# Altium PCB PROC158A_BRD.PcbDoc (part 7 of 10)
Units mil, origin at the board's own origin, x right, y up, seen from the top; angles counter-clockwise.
Board outline 3346.45 x 4921.26 mil, 8 copper layers (Top Layer, GND1, SIG1, PWR1, PWR2, SIG2, GND2, Bottom Layer), stack 54.534 mil thick; 718 components, 459 nets, 2307 pads, 1179 vias.
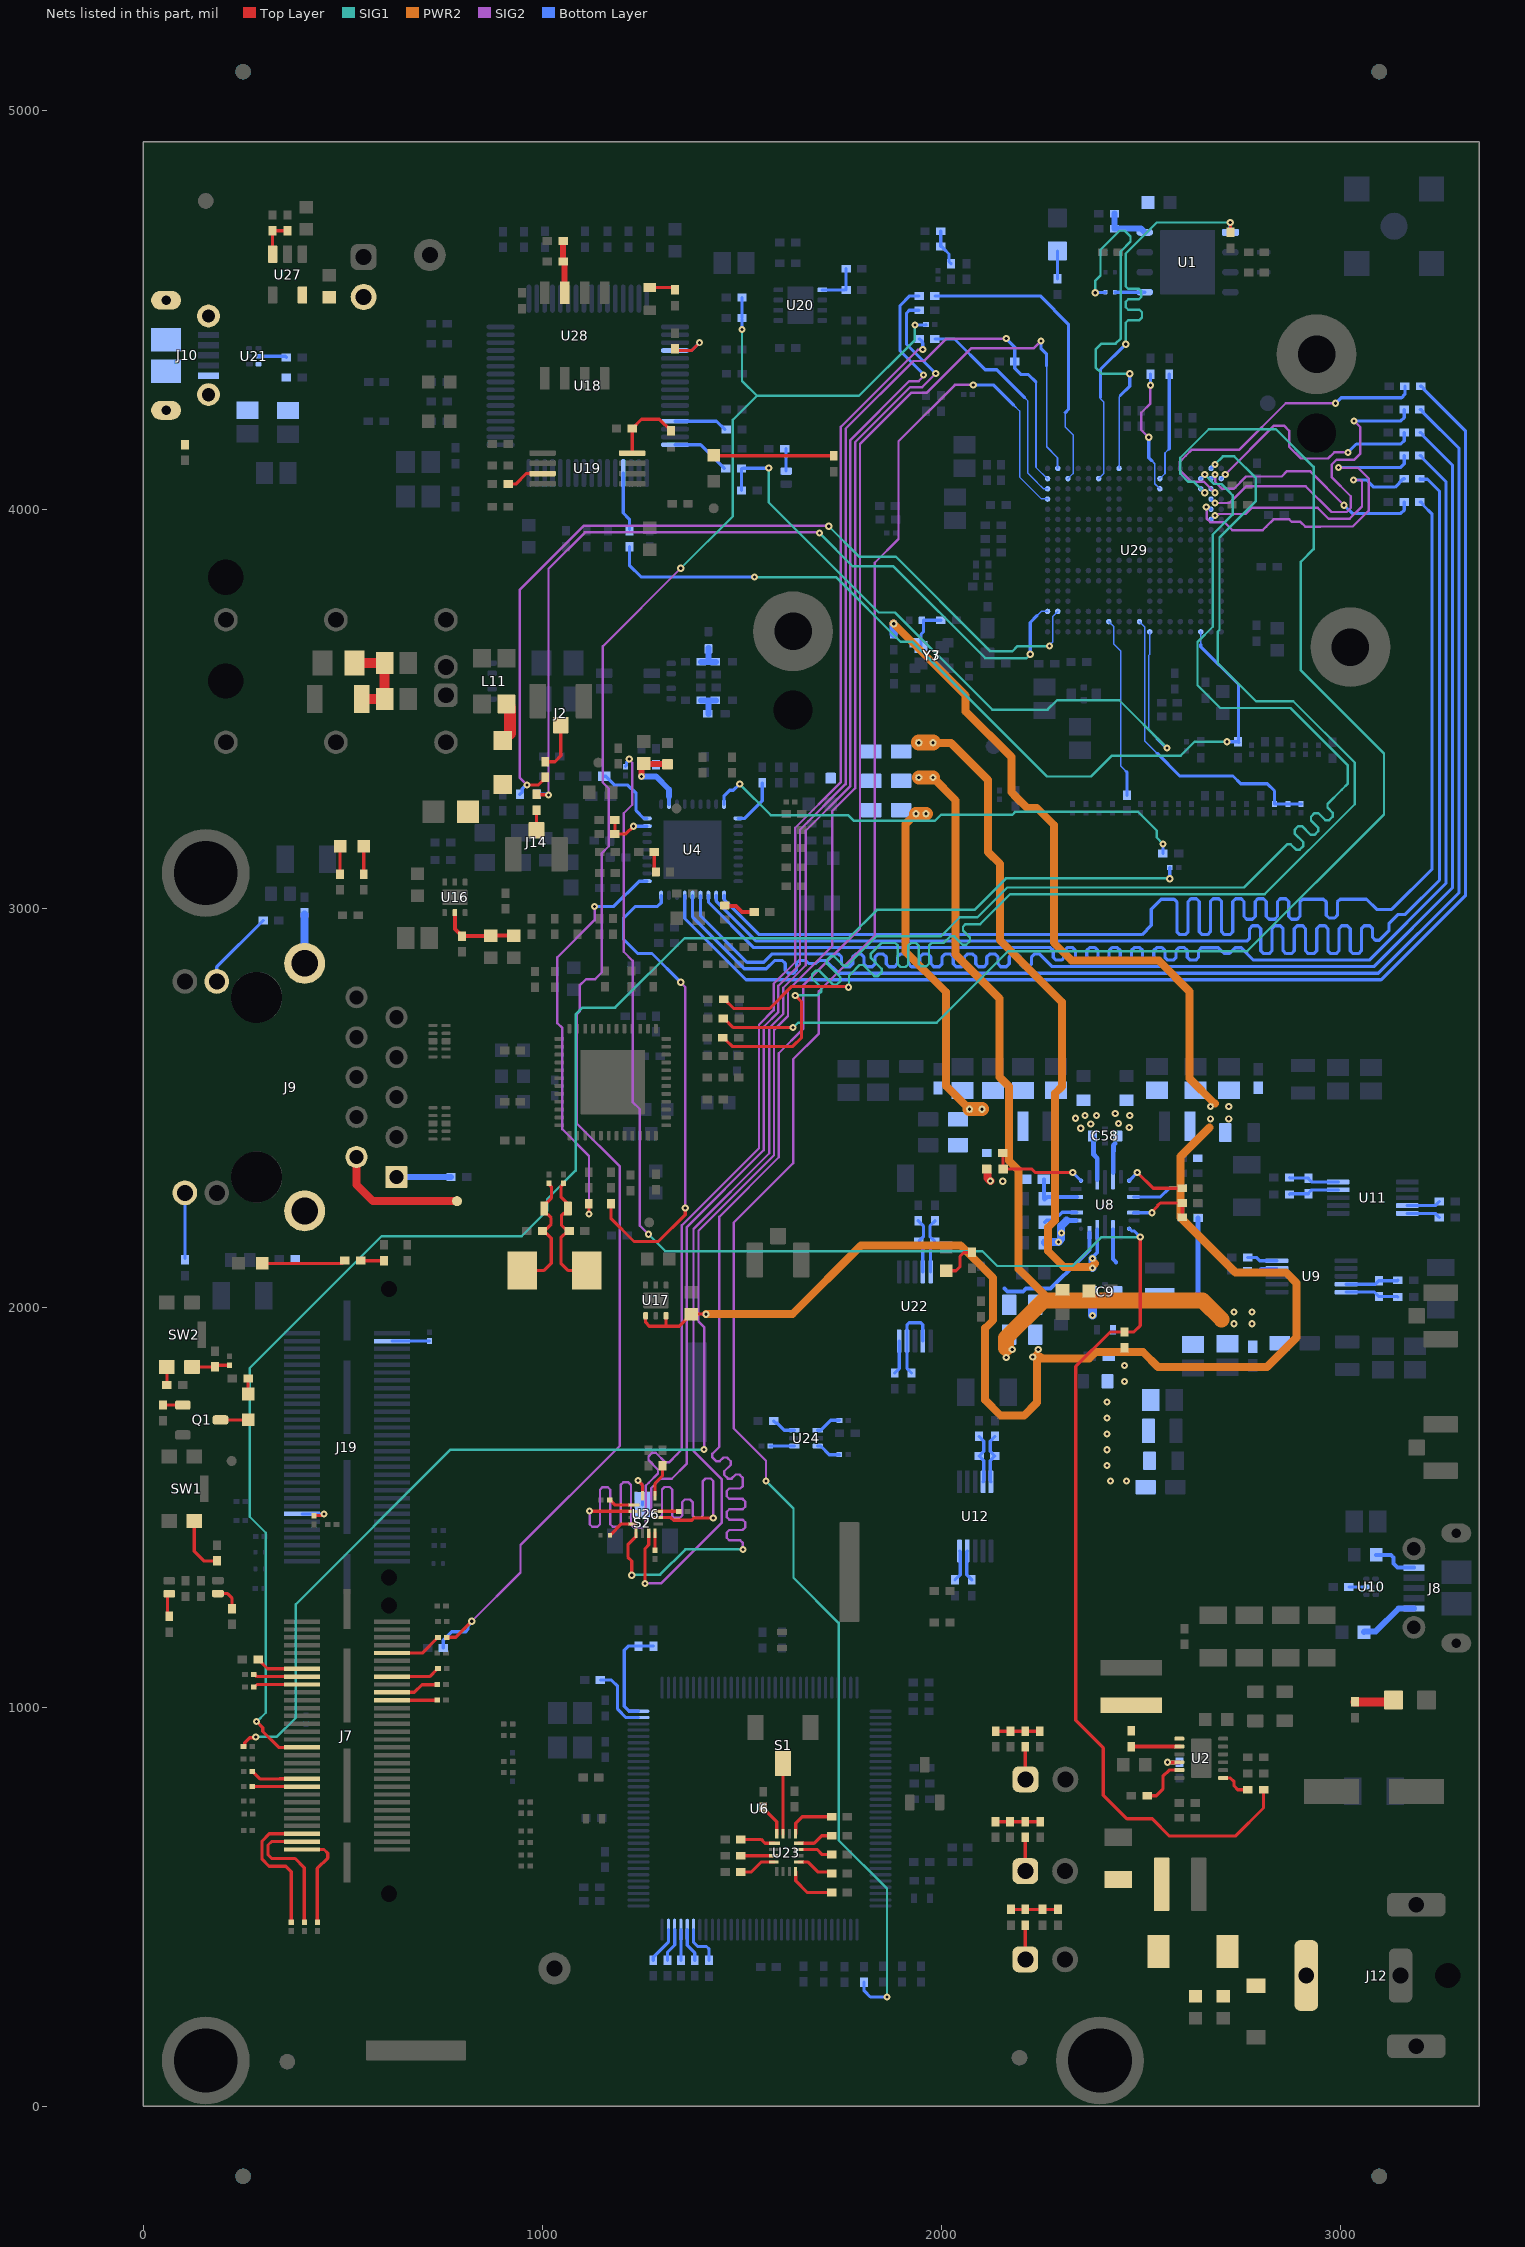
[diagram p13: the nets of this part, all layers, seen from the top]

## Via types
v1: diameter 18, hole 8, Top Layer to Bottom Layer, tented both sides, 1112 vias
v2: diameter 19.68, hole 7.87, Top Layer to Bottom Layer, 28 vias
v3: diameter 20, hole 10, Top Layer to Bottom Layer, tented both sides, 26 vias
v4: diameter 16/18/18/18/18/18/18/16 (per signal layer), hole 8, Top Layer to Bottom Layer, tented both sides, 13 vias

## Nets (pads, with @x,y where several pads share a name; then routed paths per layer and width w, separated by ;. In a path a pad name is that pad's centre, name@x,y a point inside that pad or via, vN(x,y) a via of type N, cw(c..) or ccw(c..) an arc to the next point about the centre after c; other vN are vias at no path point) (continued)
MSS_RGMII_RD1: R238.1 R336.1 U29.T16 | length 3422.1
  Top Layer w8: R336.1@1451.99,2676.6 1453.96,2676.6 1459.8,2670.76 1459.8,2670.39 1475.19,2655 1627.29,2655 1649,2676.71 1649,2767.02 v1(1633.15,2782.87)
  SIG1 w6: v1(1633.15,2782.87) 1688.91,2782.87 1696.81,2790.76 1698.93,2792.89 1698.93,2802.08 1675.22,2825.79 1675.22,2834.98 1684.41,2844.17 1693.6,2844.17 1728.07,2809.7 1737.26,2809.7 1746.45,2818.9 1746.45,2828.09 1712.53,2862.02 1712.53,2871.21 1721.72,2880.4 1730.91,2880.4 1754.08,2857.23 1763.27,2857.23 1792.19,2886.15 1837.04,2931 1998,2931 2045.45,2978.45 2089.55,2978.45 2164.23,3053.13 2757.4,3053.13 2844.95,3140.68 2865.46,3161.19 2874.65,3161.19 2887.82,3148.02 2897.02,3148.02 2906.21,3157.21 2906.21,3166.4 2884.27,3188.34 2884.27,3197.53 2893.46,3206.72 2902.66,3206.72 2924.59,3184.79 2933.79,3184.79 2942.98,3193.98 2942.98,3203.17 2925.16,3220.99 2925.16,3230.18 2934.35,3239.38 2943.54,3239.38 2961.36,3221.56 2970.56,3221.56 2979.75,3230.75 2979.75,3239.94 2966.58,3253.11 2966.58,3262.3 3002.1,3297.83 3017.79,3313.52 3017.79,3358.8 2873.94,3502.64 2698.12,3502.64 2640.9,3559.86 2640.9,3668.14 2679,3706.24 2679,3937.04 2729,3987.04 2729,4035.79 2718.86,4045.93 2700.79,4064 2682.39,4064 v4(2659.08,4087.31)
  Bottom Layer w6: U29.T16@2649.16,4077.38 v4(2659.08,4087.31)
MSS_RGMII_RD2: R239.1 R338.1 U29.R16 | length 3393.7
  Top Layer w8: R338.1@1453.43,2724.89 1455.4,2724.89 1478.29,2702 v1(1628,2702)
  SIG1 w6: v1(1628,2702) 1628.14,2702.04 1640.78,2714.68 1987.68,2714.68 2166.35,2893.35 2765.31,2893.35 3108.2,3236.24 3108.2,3388.59 2900,3596.79 2900,3869 2931.7,3900.7 2931.7,4106.7 2837.45,4200.95 2668.95,4200.95 2597.53,4129.53 2597.53,4089.49 2617.74,4069.29 2632.1,4069.29 2659.08,4042.3 v4(2659.08,4041.87)
  Bottom Layer w8: U29.R16@2649.16,4051.79 v4(2659.08,4041.87)
MSS_RGMII_RD3: R240.1 R339.1 U29.U17 | length 3379.8
  Top Layer w8: R339.1@1453.7,2773.09 1455.66,2773.09 1478.75,2750 1569.01,2750 1624.45,2805.44 1764.52,2805.44 v1(1766.91,2803.05)
  SIG1 w6: v1@1768.05,2804.11 1768.05,2832.58 1773.89,2838.41 1794.39,2858.92 1803.58,2858.92 1831.37,2831.13 1840.57,2831.13 1849.76,2840.32 1849.76,2849.52 1821.97,2877.31 1821.97,2886.5 1842.99,2907.52 1849.47,2914 1854.84,2914 1883.84,2914 1890.34,2907.5 1890.34,2860.48 1896.84,2853.98 1909.84,2853.98 1916.34,2860.48 1916.34,2907.5 1922.84,2914 1935.84,2914 1942.34,2907.5 1942.34,2862.15 1948.84,2855.65 1961.84,2855.65 1968.34,2862.15 1968.34,2907.5 1974.84,2914 1980.05,2914 1985.16,2914 2005.04,2914 2022.11,2931.07 2031.3,2931.07 2052.57,2909.8 2061.76,2909.8 2070.95,2918.99 2070.95,2928.18 2053.37,2945.76 2053.37,2954.95 2059.87,2961.45 2073.75,2961.45 2096.59,2961.45 2171.27,3036.13 2809.17,3036.13 3034.79,3261.74 3034.79,3365.84 2880.98,3519.64 2787.36,3519.64 2691.76,3615.24 2691.76,3694.11 2696,3698.34 2696,3930 2787.06,4021.06 2787.06,4079.08 2733.19,4132.95 2704.46,4132.95 2684.67,4113.16 v4(2684.67,4112.9)
  Bottom Layer w8: U29.U17@2674.75,4102.97 v4(2684.67,4112.9)
MSS_RGMII_TCLK: R74.1 R98.1 U29.T17 | length 599
  SIG2 w6: v4(2684.67,4087.31) 2685.22,4086.76 2685.22,4069.31 2702.41,4052.12 2718.86,4052.12 2732.23,4052.12 2762.8,4082.68 2851.8,4082.68 2865.32,4096.21 2922.39,4096.21 v1(3007.9,4010.7)
  Bottom Layer w8: U29.T17@2674.75,4077.38 v4(2684.67,4087.31) ; v1(3007.9,4010.7) 3028.44,3990.16 3150.38,3990.16 3158.63,3998.41 R98.1@3158.63,4019
MSS_RGMII_TCTL: R101.1 R230.1 U29.M17 | length 642.4
  SIG2 w6: v4(2684.67,3984.94) 2686.97,3987.24 2692.59,3987.24 2694.19,3988.84 2727.51,3988.84 2761.18,3988.84 2776.39,4004.05 2870,4004.05 2942.17,4004.05 2969.52,3976.7 3021.98,3976.7 3053,4007.72 3053,4070.49 3049.49,4074 v1(3032,4074)
  Bottom Layer w8: U29.M17@2674.88,3975.15 2684.19,3984.46 v4@2685.15,3984.46 ; v1(3032,4074) 3064.51,4074 3082.39,4056.13 3135.82,4056.13 3156.66,4076.97 R101.1@3158.63,4076.97
MSS_RGMII_TD0: R96.1 R103.1 U29.R17 | length 801.8
  SIG2 w6: v4(2684.67,4041.87) 2656.76,4069.78 2624.93,4069.78 2596,4098.72 2596,4119 2611.47,4134.47 2627,4150 2746,4150 2862,4266 v1(2987,4266)
  Bottom Layer w8: U29.R17@2674.75,4051.79 v4(2684.67,4041.87) ; v1(2987,4266) 3001,4280 3152.35,4280 3160.6,4288.25 R103.1@3160.6,4308.84
MSS_RGMII_TD1: R100.1 R105.1 U29.P17 | length 852.4
  SIG2 w6: v4(2684.67,4016.28) 2720.89,4016.28 2727.51,4022.89 2762.61,4058 2870,4058 2912.26,4058 2976.56,3993.7 3014.94,3993.7 3024.9,4003.66 3024.9,4033.1 2977,4081 2977,4112.04 2989.97,4125.01 3034.02,4125.01 3049.03,4140.02 3049.03,4205.97 v1(3033,4222)
  Bottom Layer w6: U29.P17@2674.75,4026.2 v4(2684.67,4016.28)
  Bottom Layer w8: v1(3033,4222) 3150.35,4222 3158.63,4230.28 R105.1@3158.63,4250.87
MSS_RGMII_TD2: R121.1 R178.1 U29.T18 | length 609.9
  SIG2 w6: v4(2710.26,4087.31) 2832.96,4210 2857.61,4210 2870.5,4197.11 2870.5,4157.09 2899.94,4127.66 2967.97,4127.66 2983.31,4143 v1(3018,4143)
  Bottom Layer w6: U29.T18@2700.34,4077.38 v4(2710.26,4087.31)
  Bottom Layer w8: v1(3018,4143) 3039,4164 3150.32,4164 3158.63,4172.31 R121.1@3158.63,4192.91
MSS_RGMII_TD3: R122.1 R225.1 U29.N17 | length 852.9
  SIG2 w6: v4@2663.83,4006.03 2663.83,3977.17 2673.06,3967.94 2708.38,3967.94 2728,3948.32 2804.28,3948.32 2812.98,3957.02 2831.28,3975.28 2870.78,3975.28 2877.18,3968.88 2898.96,3968.88 2910.69,3957.15 2948.85,3957.15 ; 2949,3957.3 3030,3957.3 3070,3997.3 3070,4077.53 3042.53,4105 v1(2994,4105)
  Bottom Layer w8: v4(2662.83,4006.03) 2664.36,4004.5 2669.31,4004.5 2673.2,4000.61 U29.N17@2674.75,4000.61 ; v1(2994,4105) 3149.29,4105 3158.63,4114.34 R122.1@3158.63,4134.94
MSS_RS232RX: R158.2 R278.1 U29.A11 | length 1789.5
  SIG1 w6: v1(1567,4103.81) 1567,4017.41 1842.41,3742 1883.57,3742 2106.08,3519.5 2126.75,3498.82 2265.37,3498.82 2288.85,3522.3 2444.88,3522.3 v1(2564.46,3402.72)
  Bottom Layer w4: U29.A11@2521.21,3693.52 2521.21,3636.96 2518.38,3634.13 2518.38,3447.5 2540.06,3425.82
  Bottom Layer w8: R278.1@1498.67,4047.24 R158.2@1498.67,4102.86 ; R158.2@1503.08,4103.33 1566.52,4103.33 v1(1567,4103.81) ; 2540.06,3425.82 2563.16,3402.72 v1(2564.46,3402.72)
MSS_RS232TX: R162.2 R279.1 U29.A16 | length 2143.5
  SIG1 w6: v1(1531.5,3830.71) 1735.52,3830.71 1897.73,3668.49 1926.95,3668.49 2106.08,3489.36 2264.31,3331.13 2374,3331.13 2426.45,3383.58 2599.01,3383.58 2633.43,3418 v1(2715,3418)
  Bottom Layer w4: 2649.16,3662.03 U29.A16@2649.16,3693.52
  Bottom Layer w8: R162.2@1217.86,3906.88 1217.86,3859.95 1247,3830.81 1531.39,3830.81 v1(1531.5,3830.71) ; 2649.16,3662.03 2649.16,3656.2 2743.68,3561.68 ; v1(2715,3418) R279.1@2742,3418.01 ; 2743.98,3561.98 2743.98,3417.02 R279.1@2745,3416
MSS_SPIA_HOSTIRQ: R18.1 R151.2 R153.2 R320.1 R326.2 | length 4454.3
  Top Layer w8: R320.1@760.24,1174.67 782.67,1174.67 v1(823,1215)
  SIG1 w6: v1(1346.44,3852.64) 1477,3983.19 1477,4224.78 1537.26,4285.04 ; v1(1500,4450.81) 1500,4322.3 1537.26,4285.04 ; v1(1933,4462) 1933,4425.02 1793.02,4285.04 1537.26,4285.04
  SIG2 w6: v1(823,1215) 945,1337 945,1405.61 1193.86,1654.47 1193.86,2354.23 1085.85,2462.24 1085.85,2735.21 1093.22,2742.57 1093.22,2807.22 1109.41,2823.41 1131.89,2823.41 1148.72,2840.25 1148.72,2981.42 1149,2981.7 1149,3139.3 1166.12,3156.42 1166.12,3301.18 1151,3316.3 1151,3657.19 v1(1346.44,3852.64)
  Bottom Layer w8: R326.2@751.69,1147.81 751.69,1167.5 772.98,1188.79 807.79,1188.79 813.45,1194.45 813.45,1202.74 823,1212.29 v1(823,1215) ; R153.2@1499.8,4479.83 R151.2@1499.8,4531.01 ; R153.2@1499.9,4475.99 1499.9,4450.91 v1(1500,4450.81) ; v1(1933,4462) 1933.5,4462.5 1960.45,4462.5 R18.1@1960.95,4463
MSS_SPIB_CLK: R380.1 U26.2 | length 4027.5
  Top Layer w8: v1(1118.22,1490.84) 1118.76,1490.31 U26.2@1226.81,1490.31
  SIG2 w6: v1(1118.22,1490.84) 1118.22,1458.1 1124.72,1451.6 1137.72,1451.6 1144.11,1457.99 1144.11,1544.39 1150.61,1550.89 1163.61,1550.89 1169.99,1544.51 1169.99,1458.1 1176.49,1451.6 1189.49,1451.6 1195.87,1457.99 1195.87,1556.39 1202.37,1562.89 1215.37,1562.89 1221.75,1556.51 1221.75,1457.27 1229.62,1449.4 1250.41,1449.4 1258.34,1457.33 1258.34,1554.34 1266.12,1562.12 1289.5,1585.5 1289.5,1594.69 1265.56,1618.63 1265.56,1627.82 1274.76,1637.02 1283.95,1637.02 1307.89,1613.08 1317.08,1613.08 1337.59,1633.59 1349,1645 1349,2206.6 1542.45,2400.05 1542.45,2709.33 1579.15,2746.03 1579.15,2811.86 1633.18,2865.89 1633.18,3202.78 1747.5,3317.1 1747.5,4207.11 1940.12,4399.73 1951.77,4399.73 v1(1952.68,4400.63)
  Bottom Layer w8: R380.1@1943.63,4427 1945.6,4427 1951.44,4421.16 1951.44,4417.71 1952.68,4416.47 v1(1952.68,4400.63)
MSS_SPIB_CS0: R273.1 U26.10 U29.T1 | length 4545.7
  Top Layer w8: U26.10@1289.8,1474.56 1321.57,1474.56 1328.21,1467.92 1373.8,1467.92 1379.7,1473.81 v1(1428,1473.81)
  SIG2 w6: v1(1428,1473.81) 1428,1566.24 1421.62,1572.62 1408.38,1572.62 1402,1566.24 1402,1480.31 1395.5,1473.81 1382.5,1473.81 1376.12,1480.19 1376.12,1513.6 1369.62,1520.1 1356.62,1520.1 1350.24,1513.72 1350.24,1480.31 1343.74,1473.81 1330.74,1473.81 1325.35,1479.2 1325.35,1544.71 1318.85,1551.21 1305.85,1551.21 1299.47,1544.83 1299.47,1481.3 1291.98,1473.81 1278.98,1473.81 1272.59,1480.19 1272.59,1548.6 1295.76,1571.76 1323.76,1571.76 1361,1609 1361,2201.63 1554.45,2395.08 1554.45,2704.36 1591.15,2741.06 1591.15,2806.89 1645.18,2860.92 1645.18,3197.81 1759.5,3312.13 1759.5,4202.14 1929.36,4372 1956,4372 2012.02,4428.02 v1(2161.67,4428.02)
  Bottom Layer w4: 2235.98,4319.55 2236.31,4319.22 2236.31,4105.47 2264.39,4077.38 U29.T1@2265.3,4077.38
  Bottom Layer w8: v1(2161.67,4428.02) 2183.37,4406.31 R273.1@2183.37,4371 2183.37,4353.63 2199.06,4337.94 2217.59,4337.94 2235.98,4319.55
MSS_SPIB_CS1: R55.1 R215.1 | length 4815
  Top Layer w8: R215.1@250.98,900.81 251.76,900.81 254.06,903.11 254.06,910.79 266.53,923.26 279.86,923.26 v1(281.77,925.17)
  SIG1 w6: v1(281.77,925.17) 334.18,925.17 382,972.99 382,1257.24 769.76,1645 v1(1405,1645)
  SIG2 w6: v1(1405,1645) 1405,1951.94 1390.92,1966.02 1390.92,2193.17 1580,2382.26 1580,2695.96 1615.15,2731.12 1615.15,2795.87 1726.09,2906.81 1726.09,3244.79 1783.5,3302.19 1783.5,4169.01 1920.88,4306.38 1951.16,4306.38 v1(1985.39,4340.61)
  Bottom Layer w8: R55.1@1943.63,4499 1919,4499 1911.98,4491.98 1911.98,4414.02 v1(1985.39,4340.61)
MSS_SPIB_MISO: U26.5 U29.U2 | length 4567
  Top Layer w8: v1(1223.8,1330.39) 1223.8,1365.98 1214.04,1375.73 1214.04,1406.8 1234.69,1427.44 U26.5@1234.69,1435.19
  SIG1 w6: v1(1223.8,1330.39) 1225.28,1331.87 1294.87,1331.87 1358,1395 v1@1501.4,1395
  SIG2 w6: v1(1502,1395) 1502,1407.96 1502,1410.96 1495.5,1417.46 1468.09,1417.46 1461.59,1423.96 1461.59,1436.96 1468.09,1443.46 1501.5,1443.46 1508,1449.96 1508,1462.96 1501.5,1469.46 1468.09,1469.46 1461.59,1475.96 1461.59,1488.96 1468.09,1495.46 1501.5,1495.46 1508,1501.96 1508,1514.96 1501.5,1521.46 1468.09,1521.46 1461.59,1527.96 1461.59,1540.96 1468.09,1547.46 1495.5,1547.46 1502,1553.96 1502,1558 1502,1574 1495.5,1580.5 1493.38,1582.62 1484.19,1582.62 1473.85,1572.28 1464.65,1572.28 1455.46,1581.48 1455.46,1590.67 1471.56,1606.77 1471.56,1615.96 1462.37,1625.15 1453.17,1625.15 1444.13,1616.11 1434.94,1616.11 1425.75,1625.3 1425.75,1634.49 1443.18,1651.93 1443.18,1688.18 1443.18,2228.47 1592,2377.29 1592,2637.97 1653,2698.97 1653,2807.88 1795.5,2950.38 1795.5,4164.04 1923.45,4291.98 1962.21,4291.98 2073.7,4403.47 2230.42,4403.47 v1(2249.15,4422.19)
  Bottom Layer w4: 2262.98,4359.55 2262.98,4157.17 2290.19,4129.96 2290.19,4103.68 U29.U2@2290.89,4102.97
  Bottom Layer w8: v1(2249.15,4422.19) 2249.15,4402.5 2262.98,4388.67 2262.98,4359.55
MSS_SPIB_MOSI: R381.1 U26.7 | length 3799.1
  Top Layer w8: v1(1256.51,1309.77) 1257,1310.26 1257,1397.07 1266.18,1406.26 U26.7@1266.18,1435.19
  SIG2 w6: v1(1256.51,1309.77) 1297.17,1309.77 1449.59,1462.19 1449.59,1570.38 1378.29,1641.67 1378.29,2197.52 1568,2387.23 1568,2700.93 1603.15,2736.09 1603.15,2801.92 1659.73,2858.49 1659.73,3195.39 1771.5,3307.16 1771.5,4173.98 1918.63,4321.11 1942.38,4321.11 1954.89,4333.62 v1(1954.89,4336.87)
  Bottom Layer w8: R381.1@1943.63,4535 1919.82,4535 1895.68,4510.86 1895.68,4397.45 1954.89,4338.24 v1(1954.89,4336.87)
MSS_UARTA_RX: R129.1 U29.P1 | length 4958.9
  SIG1 w6: v1(1560,1566) 1628.95,1497.05 1628.95,1324.05 1742,1211 1742,1155 1742,666.57 1863,545.57 v1(1863,274)
  SIG2 w6: v1(1560,1566) 1560,1617.03 1479.18,1697.85 1479.18,2213.56 1628,2362.38 1628,2622.97 1692.61,2687.58 1692.61,2793.27 1832.5,2933.15 1832.5,3866.5 1892,3926 1892,3986.8 1892,4170.86 2033.28,4312.13 v1(2079.02,4312.13)
  Bottom Layer w4: 2179.58,4262.32 2195.21,4246.69 2195.21,4081.46 2250.23,4026.44 2265.06,4026.44 U29.P1@2265.3,4026.2
  Bottom Layer w8: R129.1@1805.76,310.62 1805.76,289.33 1821.48,273.6 v1@1863,273.6 ; v1(2079.02,4312.13) 2129.76,4312.13 2179.58,4262.32
NC_50MHz: C106.1 R83.2 Y3.1 Y7.1 | length 112.9
  Bottom Layer w8: Y3.1@1948.31,3655.6 1948.31,3687.1 1954.31,3693.1 1954.31,3722.51 R83.2@1997.86,3722.51
NERR_MCU: R54.2 R111.2 U8.19 | length 242
  Top Layer w8: R54.2@2152.69,2387.81 2153.34,2387.16 R111.2@2153.34,2353.46 ; R111.2@2153.98,2347.81 2226,2347.81 2234.65,2339.16 v1(2328.32,2339.16)
  Bottom Layer w8: v1(2328.32,2339.16) 2328.48,2339.16 2349.1,2318.54 U8.19@2349.26,2318.54
NetC1_2: C1.2 C2.2 R37.2 U1.8 | length 117.2
  Bottom Layer w15: C2.2@2433,4741 R37.2@2433,4703.33 2499.8,4703.33 U1.8@2508.8,4694.33
NetC3_2: C3.2 R48.2 U8.17 | length 134.4
  Bottom Layer w10: R48.2@2256,2321.81 2256,2273.6 2258.13,2271.47 2264.66,2278 U8.17@2338.62,2278
NetC14_1: C14.1 R32.2 U9.10 | length 134.7
  Bottom Layer w8: U9.10@3013.19,2039.49 3084.26,2039.49 C14.1@3095.21,2028.54 3141.47,2028.54 R32.2@3142.82,2027.2
NetC14_2: C14.2 R26.2 U9.9 | length 133.8
  Bottom Layer w8: U9.9@3013.19,2059.18 3086.47,2059.18 C14.2@3095.21,2067.91 3141.47,2067.91 R26.2@3142.82,2069.26
NetC17_1: C17.1 R65.2 U11.10 | length 127.7
  Bottom Layer w8: R65.2@2871.43,2326.47 2872.77,2325.13 C17.1@2919.04,2325.13 2919.04,2323.16 2926.91,2315.28 U11.10@2993.39,2315.28
NetC17_2: C17.2 R47.2 U11.9 | length 127.7
  Bottom Layer w8: R47.2@2871.43,2284.41 2872.77,2285.76 C17.2@2919.04,2285.76 2919.04,2287.72 2926.91,2295.6 U11.9@2993.39,2295.6
NetC19_1: C19.1 R352.2 U12.10 | length 128.7
  Bottom Layer w8: U12.10@2123.47,1564.42 2121.77,1566.11 2121.77,1617.45 C19.1@2133.31,1628.99 2121.77,1640.52 2121.77,1666.14 R352.2@2133.62,1677.99
NetC19_2: C19.2 R348.2 U12.9 | length 128.7
  Bottom Layer w8: R348.2@2093.62,1677.99 2105.47,1666.14 2105.47,1640.52 C19.2@2093.94,1628.99 2105.47,1617.45 2105.47,1566.11 U12.9@2103.78,1564.42
NetC21_1: C21.1 U2.2 | length 120.6
  Top Layer w10: C21.1@2475,901.05 U2.2@2595.64,901.05
NetC21_2: C21.2 L6.1 U2.1
NetC24_2: C24.2 C52.1 C54.2 FB3.2 U4.11 | length 213.8
  Top Layer w15: v1(1248.1,3331.1) 1248.67,3331.68 1248.67,3358.36 C24.2@1254,3363.69 1254.94,3362.75 1312.06,3362.75 FB3.2@1313,3361.81
  Bottom Layer w10: U4.11@1317.15,3261.74 1317.15,3280.94
  Bottom Layer w15: v1(1248.1,3331.1) 1284.68,3331.1 1317.15,3298.64 1317.15,3281.4
NetC30_1: C30.1 R344.1 R414.1 Y4.2 | length 301.4
  Top Layer w8: R344.1@1052.75,2310.18 1046.13,2303.56 1046.13,2278.09 1063.72,2260.51 R414.1@1063.72,2249.27 1062.82,2249.27 1062.82,2246.47 1047.49,2231.15 1047.49,2207.69 1062.8,2192.39 1046.13,2175.72 1046.13,2111.43 1063.66,2093.9 Y4.2@1110.98,2093.9
NetC33_1: C33.1 R370.1 R414.2 Y4.1 | length 310.1
  Top Layer w8: Y4.1@949.56,2093.9 1004.06,2093.9 1022.1,2111.94 1022.1,2174.35 1004.06,2192.39 1021.67,2210 1021.67,2225.48 1004.67,2242.48 R414.2@1004.67,2249.27 1004.67,2257.14 1022.5,2274.97 1022.5,2303.7 R370.1@1016.02,2310.18
NetC34_2: C34.2 R293.1 R294.2 U16.2 | length 196.1
  Top Layer w10: U16.2@780.58,2989.96 780.58,2948.92 C34.2@798.3,2931.21 869.3,2931.21 R293.1@870.42,2932.33 R294.2@927.83,2932.33
NetC71_2: C71.2 R154.1 U6.96 | length 259.3
  Bottom Layer w8: U6.96@1240.63,989.49 1217.36,989.49 1204.88,1001.97 1204.88,1142.69 1215.02,1152.83 C71.2@1240.63,1152.83 R154.1@1278.34,1152.83
NetC81_1: C81.1 R66.2 U22.10 | length 141.9
  Bottom Layer w8: U22.10@1972.43,2090.17 1972.43,2156.62 C81.1@1982.27,2166.46 1970.89,2177.85 1970.89,2205.31 R66.2@1983.62,2218.04
NetC81_2: C81.2 R56.2 U22.9 | length 141.9
  Bottom Layer w8: R56.2@1941.56,2218.04 1954.29,2205.31 1954.29,2177.85 C81.2@1942.9,2166.46 1952.74,2156.62 U22.9@1952.74,2090.17
NetC86_1: C86.1 R181.1 U19.8 | length 180.5
  Top Layer w8: U19.8@1224.83,4141.24 C86.1@1224.83,4202.72 1248.1,4225.98 1293.08,4225.98 R181.1@1322.15,4196.92
NetC97_1: C97.1 R207.1 U21.6
NetC100_1: C100.1 D11.1 L5.1
NetC104_1: C104.1 C126.1 D3.2 D11.2 J12.1
NetC123_2: C123.2 U8.15 | length 91
  Bottom Layer w8: C123.2@2258.45,2214.34 2263.47,2219.36 2281.51,2219.36 2301.7,2239.55 2337.69,2239.55 U8.15@2338.62,2238.63
NetC149_2: C149.2 P1.2 U27.5
NetC155_2: C155.2 C156.1 R260.2 | length 71.7
  Bottom Layer w15: R260.2@1397.66,3618.51 C156.1@1434.7,3618.51 ; C155.2@1415.62,3652.92 1416.18,3652.36 1416.18,3618.51
NetC162_2: C162.2 C166.1 R274.1 | length 70.9
  Bottom Layer w15: R274.1@1397.66,3522.02 C162.2@1434.7,3522.02 ; C166.1@1416.18,3488.17 1416.18,3522.02
NetC167_1: C167.1 R275.1 R281.1 R282.2 | length 228.8
  Top Layer w25: R282.2@529.23,3615.44 R281.1@604.65,3615.44 R275.1@604.65,3525.09 C167.1@541.65,3525.09
NetD1_1: D1.1 R180.1 | length 63.8
  Top Layer w8: D1.1@1269.17,4556.1 1330.13,4556.1 R180.1@1332.18,4554.06
NetD2_1: D2.1 R36.2 | length 66.2
  Top Layer w8: D2.1@187,1284.33 211.24,1284.33 222,1273.57 R36.2@222,1246.81
NetD4_1: D4.1 R268.2 | length 60.1
  Top Layer w8: R268.2@64.98,1227 61,1230.97 61,1279.87 D4.1@64.98,1283.85
NetD5_1: D5.1 R362.2 | length 56
  Bottom Layer w8: D5.1@1610.48,4096.18 R362.2@1610.48,4152.19
NetD6_1: D6.1 R347.1 | length 69.7
  Bottom Layer w8: R347.1@2290,4578 D6.1@2290,4647.66
NetD7_1: D7.1 R108.1 | length 69.8
  Top Layer w8: R108.1@552.17,3086.52 D7.1@552.17,3156.33
NetD7_2: D7.2 R113.2 | length 69.8
  Top Layer w8: R113.2@493.11,3086.52 D7.2@493.11,3156.33
NetD8_1: D8.1 R120.2 | length 210.2
  Top Layer w8: D8.1@297.54,2111.43 498.1,2111.43 R120.2@504.92,2118.25
NetD9_1: D9.1 R261.1 | length 301.2
  Top Layer w8: D9.1@1429.01,4135.61 1430.21,4134.41 R261.1@1729.69,4134.41
NetD10_2: D10.2 R77.1 | length 80.4
  Top Layer w10.6: D10.2@1456.84,3008.38 1458.2,3007.02 1484.55,3007.02 1499.58,2992 R77.1@1530.47,2992
NetD12_1: D12.1 R331.1 | length 98.3
  Top Layer w22: R331.1@3035.7,1013.01 3127.2,1013.01 D12.1@3132,1017.81
NetD13_1: D13.1 R263.1 | length 38.7
  Top Layer w8: D13.1@262.47,1784.19 R263.1@262.47,1822.86
NetD13_2: D13.2 Q1.3 | length 69
  Top Layer w8: Q1.3@193.5,1719.23 D13.2@262.47,1719.23
NetD14_2: D14.2 R93.1 | length 51.9
  Top Layer w8: R93.1@1280.2,3142.2 1280.2,3095.95 D14.2@1284.2,3091.95
NetD16_1: D16.1 R191.1
NetD16_2: D16.2 L11.2 | length 101.6
  Top Layer w30: D16.2@900.51,3421.58 918.23,3439.29 918.23,3503.48 911.86,3509.85 L11.2@911.86,3513.18
NetDS2_1: DS2.1 R262.1 | length 99.1
  Top Layer w8: DS2.1@2011.69,2092.9 2035.9,2092.9 2046,2103 2046,2129 2056.1,2139.1 R262.1@2076.38,2139.1
NetFB2_1: FB2.1 R88.1 R89.1 R176.1
NetJ2_1: J2.1 R190.1 | length 122.1
  Top Layer w8: R190.1@1006.97,3368.32 1031.32,3368.32 1046,3383 J2.1@1046,3459.96
NetJ7_10: J7.10 R320.2 | length 131.7
  Top Layer w8: J7.10@623.08,1135.3 698.68,1135.3 736.41,1173.03 736.41,1173.67 737.41,1174.67 R320.2@738.05,1174.67
NetJ7_13: J7.13 R418.1 | length 119.6
  Top Layer w8: R418.1@287.7,1119.56 311.32,1095.93 J7.13@397.49,1095.93
NetJ7_15: J7.15 R422.2 | length 121
  Top Layer w8: R422.2@278.9,1082.03 284.65,1076.28 J7.15@397.46,1076.28
NetJ7_16: J7.16 R115.2 | length 122.7
  Top Layer w8: J7.16@623.08,1076.25 717.34,1076.25 R115.2@736.41,1095.32 ; R115.2@736.41,1095.37 R115.2@737.41,1096.36
NetJ7_17: J7.17 R423.2 | length 121.9
  Top Layer w8: R423.2@278.71,1050.53 278.71,1051.53 279.9,1051.53 284.93,1056.56 J7.17@397.49,1056.56
NetJ7_20: J7.20 R424.1 | length 119.1
  Top Layer w8: J7.20@623.08,1036.88 679.16,1036.88 698.28,1056 R424.1@734.26,1056
NetJ7_22: J7.22 R425.1 | length 111.2
  Top Layer w8: J7.22@623.08,1017.19 R425.1@734.26,1017.19
NetJ7_33: J7.33 R5.1 | length 4145.7
  Top Layer w8: v1(283.93,963.85) 299.28,948.51 299.28,938.8 338.99,899.08 J7.33@397.49,899.08
  SIG1 w6: v1(283.93,963.85) 285.1,963.85 307,985.75 307,1436.7 266.76,1476.94 266.76,1849.13 597.09,2179.46 947.9,2179.46 1011.96,2243.52 1011.96,2272.69 1083.01,2343.73 1083.01,2734.85 1100.34,2752.18 1181.9,2752.18 1355.71,2926 1766.86,2926 1837.86,2997 2081.97,2997 2160.97,3076 2570.39,3076 v1(2571.36,3075.03)
  Bottom Layer w8: v1(2571.36,3075.03) 2571.45,3075.13 2571.45,3102.9 R5.1@2571.55,3103
NetJ7_41: J7.41 R328.2 | length 131.6
  Top Layer w8: R328.2@273.38,838.88 292.19,820.08 340.66,820.08 ; 340.93,820.34 J7.41@397.49,820.34
NetJ7_43: J7.43 R329.2 | length 122.1
  Top Layer w8: R329.2@275.35,800.66 J7.43@397.49,800.66
NetJ7_55: J7.55 R197.2 | length 365.8
  Top Layer w8: R197.2@370.69,461.02 370.69,587.26 356.95,601 314.87,601 297.59,618.28 297.59,664.53 315.61,682.55 J7.55@397.49,682.55
NetJ7_57: J7.57 R198.2 | length 353.7
  Top Layer w8: J7.57@397.49,662.86 397.36,663 321.21,663 312.59,654.38 312.59,629.98 321.97,620.61 380.39,620.61 403.34,597.66 R198.2@403.34,461.02
NetJ7_59: J7.59 R114.2 | length 252.1
  Top Layer w8: J7.59@397.49,643.18 452.82,643.18 462,634 462,621.73 436,595.73 R114.2@436,461.02
NetJ8_1: J8.1 R161.1 | length 116.6
  Bottom Layer w10: R161.1@3088.52,1381.17 3125.36,1381.17 3132.45,1374.09 3132.45,1359.08 3142.31,1349.22 J8.1@3183.07,1349.22
NetJ8_5: J8.5 R175.2 | length 149.6
  Bottom Layer w15: R175.2@3058.01,1187.69 3059.89,1189.56 3087.47,1189.56 3144.77,1246.86 J8.5@3183.07,1246.86
NetJ9_1: J9.1 R400.1 | length 136.7
  Bottom Layer w15: J9.1@634.18,2327.93 R400.1@770.84,2327.93
NetJ9_2: J9.2 TP6.1 | length 338.4
  Top Layer w20: J9.2@534.18,2377.93 534.18,2308.46 575.32,2267.32 TP6.1@786.03,2267.32
NetJ9_11: J9.11 R69.1 | length 200.9
  Bottom Layer w8: J9.11@184.18,2817.7 184.18,2854.17 R69.1@300.41,2970.41
NetJ9_14: J9.14 R68.2 | length 164
  Bottom Layer w8: R68.2@104.25,2124.16 J9.14@104.25,2288.17
NetJ9_15: J9.15 R401.1
NetJ9_16: J9.16 R419.1 | length 122.8
  Bottom Layer w20: R419.1@403.86,2985.56 403.86,2863.36 J9.16@404.25,2862.97
NetJ10_1: J10.1 R206.1
NetJ10_6: J10.6 J10.7 J10.8 J10.9 J10.10 J10.11 R209.2
NetJ14_1: J14.1 R95.1 | length 50.8
  Top Layer w8: J14.1@985,3196.28 R95.1@985,3247.13
NetJ17_1: J17.1 R300.2 | length 85.8
  Top Layer w8: J17.1@2209.53,367.91 R300.2@2209.53,453.72
NetJ18_1: J18.1 R306.2 | length 84.4
  Top Layer w8: J18.1@2209.53,589.17 R306.2@2209.53,673.54
NetJ19_13: J19.13 R72.2 | length 89.4
  Top Layer w8: R72.2@427.98,1479.57 448.01,1479.57 v1(452.42,1483.98)
  Bottom Layer w8: J19.13@397.49,1483.81 456.43,1483.81 456.5,1483.88 452.52,1483.88 v1(452.42,1483.98)
NetJ19_58: J19.58 R196.1 | length 93.8
  Bottom Layer w8: J19.58@623.08,1916.88 R196.1@716.86,1916.88
NetJ20_1: J20.1 R311.2 | length 81.2
  Top Layer w8: J20.1@2209.53,818.98 R311.2@2209.53,900.17
NetQ1_1: Q1.1 R266.2 | length 49.5
  Top Layer w8: R266.2@49.46,1756.63 Q1.1@99.01,1756.63
NetR1_1: R1.1 U2.5 | length 126.3
  Top Layer w8: R1.1@2514.66,777.76 2537.53,777.76 2554.36,794.59 2554.36,826.57 2569.78,842 U2.5@2595.64,842
NetR2_2: R2.2 U2.4 | length 59.8
  Top Layer w10: v1(2565.72,861.68) U2.4@2595.64,861.68
  Bottom Layer w10: v1(2565.72,861.68) R2.2@2595.64,861.68
NetR3_2: R3.2 U29.R12 | length 316.6
  SIG2 w6: v1(2519,4181) 2518.13,4181 2500,4199.13 2500,4242.34 2523,4265.34 v1(2523,4311.25)
  Bottom Layer w4: 2526.13,4122.47 2533.97,4114.64 2533.97,4064.62 U29.R12@2546.8,4051.79
  Bottom Layer w8: v1(2519,4181) 2519,4129.61 2526.13,4122.47 ; v1(2523,4311.25) R3.2@2523,4339
NetR4_2: R4.2 U2.7 | length 80.5
  Top Layer w8: U2.7@2705.09,822.31 2723.43,822.28 2732.62,813.09 2732.62,802.19 2742,792.81 R4.2@2767,792.81
NetR6_2: R6.2 U4.18 | length 1250.9
  SIG1 w6: v1(1494.02,3312.45) 1572.09,3234.38 1765.64,3234.38 1780.21,3219.81 1982.77,3219.81 1998.38,3235.43 2177.5,3235.43 2185.26,3243.18 2491.33,3243.18 2538.84,3195.67 2538.84,3178.36 v1(2554.85,3162.35)
  Bottom Layer w8: U4.18@1454.94,3261.74 1454.94,3282.76 1468.83,3296.64 1478.21,3296.64 v1(1494.02,3312.45) v1@1495,3313.43 ; R6.2@2554.23,3138 2554.54,3138.31 2554.54,3162.04 v1(2554.85,3162.35)
NetR27_1: R27.1 U9.5 | length 76.6
  Bottom Layer w8: R27.1@2766.52,2125.82 2789.42,2125.82 2797,2118.23 U9.5@2839.96,2118.23
NetR29_1: R29.1 U9.4 | length 76.1
  Bottom Layer w8: R29.1@2766.24,2092.89 2794.08,2092.89 2799.74,2098.55 U9.4@2839.96,2098.55
NetR31_2: R31.2 U29.T12 | length 272.2
  Bottom Layer w4: U29.T12@2546.8,4078.39 U29.T12@2546.8,4077.38 2559.63,4090.21 2559.63,4134.18 2559.63,4134.47 2559.63,4141.63 2570,4152
  Bottom Layer w8: 2570,4152 R31.2@2570,4339
NetR33_1: R33.1 U11.5 | length 84.6
  Bottom Layer w8: U11.5@3166.61,2236.54 3236.84,2236.54 R33.1@3247,2226.39
NetR35_1: R35.1 U11.4 | length 84.6
  Bottom Layer w8: U11.4@3166.61,2256.23 3236.84,2256.23 R35.1@3247,2266.39
NetR50_1: R50.1 R350.1 U4.8 | length 123.4
  Top Layer w8: R50.1@1181.43,3222.28 R350.1@1181.43,3187.4 1209.08,3187.4 v1(1228.3,3206.62)
  Bottom Layer w8: v1(1228.3,3206.62) U4.8@1262.03,3206.62
NetR52_2: R52.2 U8.1 | length 157.8
  Top Layer w8: v1(2490.19,2339.02) 2529.6,2299.62 R52.2@2602.73,2299.62
  Bottom Layer w8: U8.1@2469.71,2318.54 v1(2490.19,2339.02)
NetR53_2: R53.2 U8.3 | length 131.3
  Bottom Layer w8: U8.3@2480.35,2278 2548.19,2278 2569.81,2299.62 R53.2@2602.73,2299.62
NetR57_1: R57.1 U22.5 | length 84.7
  Bottom Layer w8: R57.1@1882.53,1836.81 1893.69,1847.97 U22.5@1893.69,1916.94
NetR58_1: R58.1 U12.5 | length 78.5
  Bottom Layer w8: R58.1@2033.57,1318.67 2046.42,1331.52 2046.42,1389.5 U12.5@2044.72,1391.19
NetR59_1: R59.1 U12.4 | length 78.5
  Bottom Layer w8: U12.4@2064.41,1391.19 2062.72,1389.5 2062.72,1331.52 R59.1@2075.57,1318.67
NetR62_1: R62.1 U22.2 U22.4 | length 209.6
  Bottom Layer w8: R62.1@1924.53,1836.81 1913.37,1847.97 1913.37,1957.67 1918.24,1962.53 1947.88,1962.53 1952.74,1957.67 U22.2@1952.74,1916.94
NetR63_2: R63.2 U4.9 | length 176.5
  Bottom Layer w8: R63.2@1154.62,3331.81 1158.56,3331.81 1180.87,3309.5 1213.96,3309.5 1234.5,3288.96 1234.5,3245.65 1252.92,3227.23 1253.72,3227.23 1254.64,3226.31 U4.9@1262.03,3226.31
NetR74_2: R74.2 U4.28 | length 3694
  Bottom Layer w8: U4.28@1454.94,3033.39 1455.3,3033.04 1455.3,3022.49 1542.74,2935.05 2502.05,2935.05 2525.02,2958.02 2525.02,2998.53 2550.37,3023.88 2582.37,3023.88 2589.37,3016.88 2589.37,2942.05 2596.37,2935.05 2610.37,2935.05 2617.37,2942.05 2617.37,3018.03 2624.37,3025.03 2638.37,3025.03 2645.37,3018.03 2645.37,2942.05 2652.37,2935.05 2666.37,2935.05 2673.37,2942.05 2673.37,3018.03 2680.37,3025.03 2694.37,3025.03 2701.37,3018.03 2701.37,2942.05 2708.37,2935.05 2722.37,2935.05 2729.37,2942.05 2729.37,3018.03 2736.37,3025.03 2750.37,3025.03 2757.37,3018.03 2757.37,2980.37 2764.37,2973.37 2778.37,2973.37 2785.37,2980.37 2785.37,3018.03 2792.37,3025.03 2806.37,3025.03 2813.37,3018.03 2813.37,2980.37 2820.37,2973.37 2834.37,2973.37 2841.37,2980.37 2841.37,3018.03 2848.37,3025.03 2862.37,3025.03 2869.37,3018.03 2869.37,2980.37 2876.37,2973.37 2890.37,2973.37 2897.37,2980.37 2897.37,3016.88 2904.37,3023.88 2918.82,3023.88 2924.33,3023.88 2956.33,3023.88 2963.33,3016.88 2963.33,2983.65 2970.33,2976.65 2984.33,2976.65 2991.33,2983.65 2991.33,3016.88 2998.33,3023.88 3054.49,3023.88 3064.4,3023.88 3090,2998.28 3127.28,2998.28 3228.5,3099.5 3228.5,3988.5 3205.81,4011.19 3205.81,4013.16 3199.97,4019 R74.2@3198,4019
NetR75_1: R75.1 U4.19 | length 123.3
  Bottom Layer w8: U4.19@1490.38,3226.31 1506.67,3226.31 1550.61,3270.24 R75.1@1550.61,3315.13
NetR96_2: R96.2 U4.33 | length 3488
  Bottom Layer w8: U4.33@1356.52,3033.39 1356.52,2975.48 1509.89,2822.11 3100.98,2822.11 3312.45,3033.58 3312.45,4196.36 3207.78,4301.03 3207.78,4303 3201.94,4308.84 R96.2@3199.97,4308.84
NetR100_2: R100.2 U4.32 | length 3437.5
  Bottom Layer w8: U4.32@1376.2,3033.39 1376.2,2978.85 1505.35,2849.7 1561.04,2849.7 1581.19,2869.85 1592.01,2869.85 1601.24,2869.85 1608.24,2862.85 1608.24,2845.41 1615.24,2838.41 1629.24,2838.41 1636.24,2845.41 1636.24,2862.85 1643.24,2869.85 1647.24,2869.85 1659.73,2869.85 1666.81,2862.76 1684.89,2862.76 1691.97,2869.85 1710.36,2869.85 1741.8,2838.41 3094.03,2838.41 3296.15,3040.54 3296.15,4152.72 3205.66,4243.21 3205.66,4245.18 3199.97,4250.87 R100.2@3198,4250.87
NetR117_1: R117.1 R120.1 | length 59.1
  Top Layer w8: R120.1@544.29,2118.25 R117.1@603.35,2118.25
NetR123_1: R123.1 U6.63 | length 92.1
  Bottom Layer w8: R123.1@1277.59,365.86 1277.59,373.28 1315.44,411.13 U6.63@1315.44,442.24
NetR124_1: R124.1 U6.61 | length 76.4
  Bottom Layer w8: R124.1@1346.93,365.86 U6.61@1346.93,442.24
NetR126_1: R126.1 U6.62 | length 83.8
  Bottom Layer w8: R126.1@1313.19,365.86 1313.19,385.99 1331.18,403.98 U6.62@1331.18,442.24
NetR127_1: R127.1 U6.60 | length 84.2
  Bottom Layer w8: U6.60@1362.68,442.24 1362.68,402.96 1381.51,384.13 R127.1@1381.51,365.86
NetR152_2: R152.2 U6.95 | length 168
  Bottom Layer w8: R152.2@1145.18,1067.8 1172.57,1067.8 1188.21,1052.16 1188.21,994.89 1209.36,973.74 U6.95@1240.63,973.74
NetR156_1: R156.1 R172.2 R316.2 | length 93.1
  Bottom Layer w8: R172.2@1997.66,4696.95 R156.1@1997.66,4658.95 1999.63,4658.95 R156.1@2005.32,4653.25 ; R156.1@2005.32,4653.23 2018.5,4640.05 2018.5,4621.06 R316.2@2023.75,4615.81
NetR158_1: R158.1 U18.48 | length 147.7
  Bottom Layer w8: U18.48@1332.18,4162.05 1396.17,4162.05 R158.1@1455.36,4102.86
NetR159_2: R159.2 R409.1 U27.3 | length 93.2
  Top Layer w8: U27.3@323.96,4642.54 R159.2@323.96,4698.33 R409.1@361.36,4698.33
NetR162_1: R162.1 U18.52 | length 147.5
  Bottom Layer w8: U18.52@1202.26,4091.18 1202.26,3991.22 1217.86,3975.62 R162.1@1217.86,3950.19
NetR174_2: R174.2 U10.5 | length 43.8
  Bottom Layer w8: R174.2@3020.18,1301 U10.5@3064.01,1301
NetR178_2: R178.2 U4.31 | length 3680.1
  Bottom Layer w8: U4.31@1395.89,3033.39 1395.89,2982.21 1512.1,2866 1554.29,2866 1574.43,2886.15 1736.91,2886.15 1742.23,2886.15 1749.23,2879.15 1749.23,2861.71 1756.23,2854.71 1770.23,2854.71 1777.23,2861.71 1777.23,2879.15 1784.23,2886.15 1798.23,2886.15 1805.23,2879.15 1805.23,2861.71 1812.23,2854.71 1826.23,2854.71 1833.23,2861.71 1833.23,2879.15 1840.23,2886.15 1854.23,2886.15 1861.23,2879.15 1861.23,2861.71 1868.23,2854.71 1882.23,2854.71 1889.23,2861.71 1889.23,2879.15 1896.23,2886.15 1910.23,2886.15 1917.23,2879.15 1917.23,2861.71 1924.23,2854.71 1938.23,2854.71 1945.23,2861.71 1945.23,2879.15 1952.23,2886.15 1966.23,2886.15 1973.23,2879.15 1973.23,2861.71 1980.23,2854.71 1994.23,2854.71 2001.23,2861.71 2001.23,2879.15 2008.23,2886.15 2022.23,2886.15 2029.23,2879.15 2029.23,2861.71 2036.23,2854.71 2050.23,2854.71 2057.23,2861.71 2057.23,2879.15 2064.23,2886.15 2078.23,2886.15 2085.23,2879.15 2085.23,2861.71 2092.23,2854.71 2106.23,2854.71 2113.23,2861.71 2113.23,2879.15 2120.23,2886.15 2134.23,2886.15 2141.23,2879.15 2141.23,2861.71 2148.23,2854.71 2162.23,2854.71 2169.23,2861.71 2169.23,2879.15 2176.23,2886.15 2190.23,2886.15 2197.23,2879.15 2197.23,2861.71 2204.23,2854.71 2218.23,2854.71 2225.23,2861.71 2225.23,2879.15 2232.23,2886.15 2233.62,2886.15 ; 2233.65,2886.12 2236.23,2886.12 2245.9,2886.12 2277.01,2855 3082.56,2855 3279.85,3052.29 3279.85,4111.06 3205.81,4185.09 3205.81,4187.06 3199.97,4192.91 R178.2@3198,4192.91
NetR179_1: R179.1 U18.36 | length 138.9
  Top Layer w8: R179.1@1332.18,4398.27 1373.79,4398.27 v1(1393.47,4417.95)
  Bottom Layer w8: U18.36@1332.18,4398.27 1373.79,4398.27 v1(1393.47,4417.95)
NetR188_1: R188.1 U26.8 | length 42.1
  Top Layer w8: R188.1@1281.93,1393.06 U26.8@1281.93,1435.19
NetR194_2: R194.2 U6.59 | length 106
  Bottom Layer w8: U6.59@1378.43,442.24 1378.43,410.69 1388.96,400.15 1410.85,400.15 1417.54,393.47 R194.2@1417.54,365.27
NetR202_1: R202.1 R203.1 U20.5 | length 108.7
  Bottom Layer w8: U20.5@1701.01,4550.19 R203.1@1756.73,4550.19 ; R203.1@1760.66,4550.19 R202.1@1760.66,4603.23
NetR205_2: R205.2 U19.3 | length 98.6
  Top Layer w8: R205.2@914.04,4060.58 917.16,4063.7 933.16,4063.7 959.53,4090.06 U19.3@1000.42,4090.06
NetR208_2: R208.2 U21.5 | length 71
  Bottom Layer w8: U21.5@288.63,4383.75 355.98,4383.75 R208.2@358.57,4381.16
NetR222_1: R222.1 U24.3 | length 61.5
  Bottom Layer w8: R222.1@1579.39,1716.46 1585.08,1710.77 1588.37,1710.77 1605.81,1693.34 U24.3@1631.34,1693.34
NetR223_1: R223.1 U26.11 | length 51.6
  Top Layer w8: U26.11@1289.8,1490.31 R223.1@1341.43,1490.31
NetR225_2: R225.2 U4.30 | length 3437.6
  Bottom Layer w8: U4.30@1415.57,3033.39 1415.93,3033.04 1415.93,3015.76 1529.24,2902.45 2240.37,2902.45 2244.37,2902.44 2272.37,2902.42 2279.37,2895.42 2279.37,2878.3 2286.37,2871.3 2300.37,2871.3 2307.37,2878.3 2307.37,2895.45 2314.37,2902.45 2328.37,2902.45 2335.37,2895.45 2335.37,2878.3 2342.37,2871.3 2356.37,2871.3 2363.37,2878.3 2363.37,2895.45 2370.37,2902.45 2384.37,2902.45 2391.37,2895.45 2391.37,2878.3 2398.37,2871.3 2412.37,2871.3 2419.37,2878.3 2419.37,2895.45 2426.37,2902.45 2440.37,2902.45 2447.37,2895.45 2447.37,2878.3 2454.37,2871.3 2468.37,2871.3 2475.37,2878.3 2475.37,2895.45 2482.37,2902.45 2496.37,2902.45 2503.37,2895.45 2503.37,2878.3 2510.37,2871.3 2524.37,2871.3 2531.37,2878.3 2531.37,2895.45 2538.37,2902.45 2552.37,2902.45 2559.37,2895.45 2559.37,2878.3 2566.37,2871.3 2580.37,2871.3 2587.37,2878.3 2587.37,2895.45 2594.37,2902.45 2608.37,2902.45 2615.37,2895.45 2615.37,2878.3 2622.37,2871.3 2636.37,2871.3 2643.37,2878.3 2643.37,2895.06 2650.37,2902.06 2656.63,2902.05 2660.63,2902.05 2661.29,2902.05 2693.29,2902.05 2700.29,2895.05 2700.29,2894.76 2707.29,2887.76 2721.29,2887.76 2728.29,2894.76 2728.29,2895.05 2735.29,2902.05 2743.1,2902.05 2750.45,2902.05 2781.2,2871.3 3071.59,2871.3 3263.55,3063.26 3263.55,4069.39 3205.81,4127.13 3205.81,4129.09 3199.97,4134.94 R225.2@3198,4134.94
NetR230_2: R230.2 U4.29 | length 3647.7
  Bottom Layer w8: U4.29@1435.26,3033.39 1435.61,3033.04 1435.61,3019.12 1535.99,2918.75 2760.15,2918.75 2764.5,2918.75 2771.5,2925.75 2771.5,2950.07 2778.5,2957.07 2792.5,2957.07 2799.5,2950.07 2799.5,2894.6 2806.5,2887.6 2820.5,2887.6 2827.5,2894.6 2827.5,2950.07 2834.5,2957.07 2848.5,2957.07 2855.5,2950.07 2855.5,2894.6 2862.5,2887.6 2876.5,2887.6 2883.5,2894.6 2883.5,2950.07 2890.5,2957.07 2904.5,2957.07 2911.5,2950.07 2911.5,2894.6 2918.5,2887.6 2932.5,2887.6 2939.5,2894.6 2939.5,2950.07 2946.5,2957.07 2960.5,2957.07 2967.5,2950.07 2967.5,2894.6 2974.5,2887.6 2988.5,2887.6 2995.5,2894.6 2995.5,2950.07 3002.5,2957.07 3016.5,2957.07 3023.5,2950.07 3023.5,2894.6 3030.5,2887.6 3044.5,2887.6 3051.5,2894.6 3051.5,2950.07 3058.5,2957.07 3072.5,2957.07 3079.5,2950.07 3079.5,2927.76 3086.5,2920.76 3096.4,2920.76 3111.5,2935.86 3120.34,2944.71 3120.34,2962.38 3143.55,2985.58 3161.22,2985.58 3247.25,3071.61 3247.25,4045.78 3217.12,4075.9 3199.06,4075.9 R230.2@3198,4076.97
NetR247_2: R247.2 U4.36 | length 1231.7
  Top Layer w8: R247.2@1171.49,2261.12 1171.45,2261.07 1171.45,2224.29 1229.43,2166.31 1290.51,2166.31 1357.6,2233.4 v1(1357.6,2249.9)
  SIG2 w6: v1(1346.4,2815.8) 1346.4,2814.8 1357.6,2803.6 v1(1357.6,2249.9)
  Bottom Layer w8: U4.36@1297.46,3033.39 1297.46,3014.87 1287.97,3005.38 1232.05,3005.38 1203.1,2976.42 1203.1,2923.22 1238.55,2887.78 1274.42,2887.78 v1(1346.4,2815.8)
NetR249_2: R249.2 U4.1 | length 1026.4
  Top Layer w8: R249.2@1116.04,2261.12 1116.37,2260.78 1116.37,2235.34 v1(1116.71,2235)
  SIG2 w6: v1(1116.71,2235) 1116.71,2380.47 1049.85,2447.33 1049.85,2700.72 1037.08,2713.5 1037.08,2878.06 1130.52,2971.49 v1(1130.52,3005.68)
  Bottom Layer w8: v1(1130.52,3005.68) 1178.84,3005.68 1241.99,3068.83 U4.1@1262.03,3068.83
NetR267_2: R267.2 SW1.2 | length 143.3
  Top Layer w8: SW1.2@127.97,1466.29 127.97,1390.03 151.71,1366.29 R267.2@185.16,1366.29
NetR283_1: R283.1 U26.13 | length 82.1
  Top Layer w8: U26.13@1281.93,1529.68 1281.99,1529.74 1281.99,1560.38 1300.63,1579.02 R283.1@1300.63,1604.02
NetR296_1: R296.1 U23.13 | length 123.5
  Top Layer w8: U23.13@1634.31,682.49 1634.31,709.12 1650.41,725.22 R296.1@1724.52,725.22
NetR298_1: R298.1 R299.2 R300.1 R302.2 | length 117.8
  Top Layer w8: R298.1@2173.8,493.09 R300.1@2209.53,493.09 R302.2@2252.26,493.09 R299.2@2291.63,493.09
NetR304_1: R304.1 R305.2 R306.1 R307.2 | length 112.3
  Top Layer w8: R305.2@2134.62,712.91 R304.1@2171.6,712.91 R306.1@2209.53,712.91 R307.2@2246.93,712.91
NetR308_1: R308.1 R310.2 R311.1 R313.2 | length 110.1
  Top Layer w8: R310.2@2135.56,939.54 R308.1@2172.54,939.54 R311.1@2209.53,939.54 R313.2@2245.64,939.54
NetR317_2: R317.2 U24.4 | length 64.8
  Bottom Layer w8: U24.4@1689.61,1693.34 1696.9,1693.34 1721.99,1718.43 R317.2@1744.05,1718.43
NetR318_2: R318.2 U24.1 | length 60.6
  Bottom Layer w8: R318.2@1570.72,1653.97 U24.1@1631.34,1653.97
NetR319_1: R319.1 U24.6 | length 63
  Bottom Layer w8: U24.6@1689.61,1653.97 1696.9,1653.97 1718.58,1632.28 R319.1@1743.61,1632.28
NetR333_1: R333.1 SW2.4 | length 44.9
  Top Layer w8: R333.1@59.15,1807.13 SW2.4@59.15,1852.07
NetR334_1: R334.1 R335.2 SW2.2 | length 95.6
  Top Layer w8: SW2.2@122.14,1852.07 R335.2@179.39,1852.07 183.74,1856.42 R334.1@215.95,1856.42
NetR353_2: R353.2 U23.16 | length 80.1
  Top Layer w8: R353.2@1553.23,748.53 1553.23,746.56 1577.97,721.81 1587.06,712.75 U23.16@1587.06,682.49
NetR354_2: R354.2 U23.1 | length 88.3
  Top Layer w8: R354.2@1496.85,668.58 1547.69,668.58 1557.4,658.87 U23.1@1581.16,658.87
NetR355_2: R355.2 U23.3 | length 82.3
  Top Layer w8: R355.2@1496.85,627.37 1558.02,627.37 U23.3@1579.19,627.37
NetR356_2: R356.2 U23.4 | length 92.7
  Top Layer w8: R356.2@1496.85,586.58 1522.44,586.58 1547.49,611.62 U23.4@1579.19,611.62
NetR357_2: R357.2 U23.9 | length 92.7
  Top Layer w8: U23.9@1642.18,611.62 1665.47,611.62 1690.52,586.58 R357.2@1724.52,586.58
NetR358_2: R358.2 U23.8 | length 125.7
  Top Layer w8: U23.8@1634.31,588 1634.31,564.5 1663.23,535.58 R358.2@1724.52,535.58
NetR359_2: R359.2 U23.12 | length 90.2
  Top Layer w8: U23.12@1642.18,658.87 1680.45,658.87 1699.39,677.81 R359.2@1724.52,677.81
NetR360_2: R360.2 U23.11 | length 87.6
  Top Layer w8: U23.11@1642.18,643.12 1688.32,643.12 1701.04,630.4 R360.2@1724.52,630.4
NetR377_2: R377.2 U26.4 | length 70.1
  Top Layer w8: R377.2@1169.11,1430.27 1169.11,1431.25 1170.03,1432.17 1171.02,1432.17 1197.66,1458.81 U26.4@1226.81,1458.81
NetR380_2: R380.2 U29.R1 | length 543.8
  Bottom Layer w4: 2206.99,4281 2216.21,4271.78 2216.21,4090.69 2238.73,4068.17 2239.05,4067.85 2255.06,4051.84 2265.25,4051.84 U29.R1@2265.3,4051.79
  Bottom Layer w8: R380.2@1983,4427 2032.32,4427 2109.17,4350.15 2122.84,4350.15 2137.84,4350.15 2206.99,4281
NetR381_2: R381.2 U29.T3 | length 767.4
  Bottom Layer w4: 2309.82,4242.8 2309.82,4206.74 2329.23,4187.33 2329.23,4108.27 2329.24,4097.69 ; U29.T3@2316.48,4077.38 2316.48,4077.48 2329.23,4090.23 2329.23,4097.67
  Bottom Layer w8: R381.2@1983,4535 2247,4535 2317.54,4464.46 2317.54,4250.52 2309.82,4242.8
NetR386_2: R386.2 U29.B7 | length 453.8
  Bottom Layer w4: U29.B7@2418.84,3719.11 2431.6,3706.35 2431.6,3662.57 2449.17,3645 2449.17,3356.83 2462,3344
  Bottom Layer w8: 2462,3344 2464,3342 R386.2@2464,3284.07
NetR399_1: R399.1 U26.1 | length 65.8
  Top Layer w8: R399.1@1168.33,1519.02 1169.11,1519.02 1182.08,1506.06 U26.1@1228.78,1506.06
NetR416_1: R416.1 R417.2 U28.7 | length 131.2
  Top Layer w15: R417.2@1051.89,4672.69 R416.1@1051.89,4620.96 1055.83,4617.02 U28.7@1055.83,4543.13
NetS1_2: S1.2 U23.15 | length 176.2
  Top Layer w8: U23.15@1602.81,682.49 S1.2@1602.81,858.71
NetS2_2: S2.2 U26.15 | length 108.6
  Top Layer w8: v1(1239.21,1567.81) 1250.43,1556.58 U26.15@1250.43,1529.68
  Bottom Layer w8: v1(1239.21,1567.81) 1250.43,1556.58 S2.2@1250.43,1506.68
NRST_FTDI: R166.1 U18.45 | length 132.8
  Bottom Layer w8: U18.45@1332.18,4221.1 1435.99,4221.1 R166.1@1456.49,4200.6
NRSTOUT: R99.2 R102.1 U8.5 | length 170.6
  Top Layer w8: v1(2526.84,2238.25) 2526.84,2240.25 2540.54,2253.95 2540.54,2255.35 2548.03,2262.84 R102.1@2602.73,2262.84 R99.2@2602.73,2226.96
  Bottom Layer w8: U8.5@2480.35,2238.63 2480.54,2238.44 2526.65,2238.44 v1(2526.84,2238.25)
OSC_CLK_OUT_25: R95.2 R241.1 U29.C1 | length 2141.6
  Top Layer w8: R95.2@985,3286.5 985.92,3285.57 1014.24,3285.57 v1(1015.16,3284.65)
  SIG1 w6: v1(1694,3941) 1777.39,3857.61 1879.39,3857.61 2109.5,3627.5 2212.49,3627.5 2222,3637.01 v1(2222,3637.5)
  SIG2 w6: v1(1015.16,3284.65) 1015.16,3851.59 1106.2,3942.64 1692.36,3942.64 v1(1694,3941)
  Bottom Layer w4: 2238.73,3733.73 2249.71,3744.71 U29.C1@2265.3,3744.71
  Bottom Layer w8: R241.1@986,3286.5 1013.32,3286.5 v1(1015.16,3284.65) ; v1(2222,3637.5) 2222,3717 2238.73,3733.73
OSC_CLKTOP: R168.1 R190.2 U29.C2 | length 2208.7
  Top Layer w8: v1(961,3310) 961.18,3309.82 989.81,3309.82 1006.97,3326.98 R190.2@1006.97,3328.95
  SIG1 w6: v1(1717,3958) 1793,3882 1885,3882 2106.08,3660.92 2122.53,3644.47 2176.79,3644.47 2190.14,3657.82 v1(2270.32,3657.82)
  SIG2 w6: v1(961,3310) 943.33,3327.67 943.33,3799.57 1102.77,3959 1716,3959 v1(1717,3958)
  Bottom Layer w4: v1@2272.31,3662.51 2278.06,3668.27 2278.06,3724.4 ; 2278.03,3724.43 2278.03,3731.84 U29.C2@2290.89,3744.71
  Bottom Layer w8: R168.1@943.33,3286.18 949.18,3292.02 949.18,3300.31 958.86,3310 v1(961,3310) ; v1(2270.32,3657.82) 2270.32,3660.52 2271.82,3662.03 v1@2272.31,3662.51
PMIC_CLK_OUT: R104.1 R218.1 R220.1 U29.B10 | length 780.9
  Bottom Layer w4: U29.B10@2495.62,3719.11 2508.38,3706.35 2508.38,3420.63 2540.06,3388.94
  Bottom Layer w8: 2540.06,3388.94 2596.5,3332.5 2729.96,3332.5 2749.46,3313 2816,3313 2833.94,3295.06 R220.1@2833.94,3262.27 R104.1@2867.31,3262.27 R218.1@2900.69,3262.27
PMIC_EN: R4.1 R12.1 R125.1 U8.7 | length 4628.9
  Top Layer w8: v1(2497.65,2177.26) 2497.65,1955.65 2481.56,1939.56 2422.18,1939.56 2336,1853.38 2336,966.81 2405,897.81 2405,779 2464,720 2527.67,720 2570.86,676.81 2736,676.81 2806.37,747.18 R4.1@2806.37,792.81
  SIG1 w6: v1(1265.63,2184.31) 1307.94,2142 2102.47,2142 2139.47,2105 2328.3,2105 2400.56,2177.26 v1(2497.65,2177.26)
  SIG2 w6: v1(1217.26,3374.9) 1217.26,3373.13 1225,3365.39 1225,3260.4 1203.52,3238.91 1203.52,3073.05 1203.52,2892 1225.8,2869.72 1225.8,2515.92 1244.17,2497.55 1244.17,2205.77 v1(1265.63,2184.31)
  Bottom Layer w8: R12.1@1208,3356.65 1210.3,3358.95 1210.3,3365.24 1217.26,3372.2 v1(1217.26,3374.9) ; U8.7@2469.71,2198.09 2470.39,2198.09 2475.87,2192.61 2482.3,2192.61 v1(2497.65,2177.26)
PMIC_LDO_1V0: C51.2 C80.2 R89.2 U8.11 | length 1711.2
  PWR2 w20: 1988.25,3414.88 2023.46,3414.88 2116.08,3322.26 2116.08,3142.29 2146,3112.37 2146,2921 2301.3,2765.7 2301.3,2554.54 2284.4,2537.64 2284.4,2219.36 2267,2201.96 2267,2141.92 2306.92,2102 2374.57,2102 2384.08,2111.52
  PWR2 w40: v1(1942.69,3415.81) v1(1978.31,3415.81)
  Bottom Layer w8: v1(2377.95,2123.78) v1@2377.95,2126.49
  Bottom Layer w10: v1@2377.95,2126.49 2389.8,2138.33 U8.11@2389.8,2195.81
  Bottom Layer w20: v1(2377.95,2100.16) v1(2377.95,2123.78)
PMICOUT_1V0: C120.1 C124.1 C132.1 C134.1 L8.2 R71.2 R176.2 R192.1 R193.1 | length 873.7
  PWR2 w20: v1(1935.72,3237.83) 1909.8,3211.9 1909.8,2892.3 2011.3,2790.8 2011.3,2556.18 v1(2069.69,2497.8)
  PWR2 w35: v1(1935.72,3237.83) v1(1960.96,3237.83) ; v1(2069.69,2497.8) v1(2101.18,2497.8)
PMICOUT_1V2: C122.1 C129.1 C130.1 L2.2 R88.2 R109.1 R110.1 R291.2 | length 2314.6
  PWR2 w20: v1(1978.31,3328.31) 2035,3271.62 2035,2885 2144.85,2775.15 2144.85,2578.08 2168.43,2554.5 2168.43,2368.57 2193,2344 2193,2097.4 2272.22,2018.18
  PWR2 w35: v1(1942.69,3328.31) v1(1978.31,3328.31)
  PWR2 w40: 2161,1900 2161,1924.5 2254.68,2018.18 2653.82,2018.18 2701,1971
  Bottom Layer w12: 2629.92,2005.67 2642.37,2018.12 R291.2@2642.37,2224.81
  other v1: 2162,1875.81 2177,1895.81 2732.28,1960.39 2777.56,1960.39 2732.28,1989.92 2777.56,1989.92
PMICOUT_1V8: C60.1 C119.1 C125.1 C127.1 L9.2 L12.1 R14.2 R87.1 R107.1 U17.4 U17.6 | length 4779.5
  Top Layer w8: U17.4@1258.35,1980.28 1258.35,1963.49 1267.68,1954.16 1311.02,1954.16 ; U17.6@1309.53,1980.28 1309.53,1955.66 1311.02,1954.16 ; v1(1409.45,1984.25) 1409.35,1984.36 1373.11,1984.36 C60.1@1373.01,1984.46 1342.71,1954.16 1311.02,1954.16
  PWR2 w20: v1(1409.45,1984.25) 1625.98,1984.25 1798,2156.27 2047.66,2156.27 2129.13,2074.8 2129.13,1969.13 2109,1949 2109,1769 2148,1730 2206,1730 2239,1763 2239,1883 ; v1(1880,3714) 2060.27,3533.73 2060.27,3494.13 2174.73,3379.67 2174.73,3291.88 2186.61,3280 2213.77,3252.84 2238.2,3252.84 2281,3210.04 2281,2914.73 2325.77,2869.97 2544.03,2869.97 2621.12,2792.88 2621.12,2574.62 2684.26,2511.47 ; 2248,1877 2252,1873 2369.76,1873 2385.84,1889.08 2505,1889.08 2542.08,1852 2815,1852 2889,1926 2889,2062.58 2863.11,2088.46 2736.4,2088.46 2598.21,2226.65 2598.21,2379.21 2671,2452
  Bottom Layer w20: R87.1@1879.89,3688.31 1880,3688.42 v1(1880,3714)
  other v1: 2228,1876.81 2242,1895.81 2673.19,2473.54 2719.19,2473.54 2673.19,2504.54 2719.19,2504.54
PVIN3V3: C6.2 C7.1 C9.1 C9.3 C15.1 C31.1 C58.1 C58.3 C143.1 C144.2 C148.2 C153.2 C199.1 C200.2 L1.2 R48.1 R111.1 R125.2 R200.2 U8.9 U8.14 U8.21 U8.23 | length 489.3
  Top Layer w20: R111.1@2112.65,2347.81 2114.46,2346 2114.46,2325.36 v1(2122,2317.81)
  Bottom Layer w10: U8.9@2429.17,2195.81 2429.17,2122.65 2436.37,2115.45 2436.37,2113.28
  Bottom Layer w12: 2313.33,2218.94 U8.14@2336.65,2218.94 ; C58.3@2377.99,2430.63 2380.57,2428.05 2380.57,2393 2380.57,2384.21 2389.8,2374.98 U8.21@2389.8,2320.81 ; U8.23@2429.82,2338.93 2429.82,2392.43 2430.4,2393 2430.4,2407.4 2435,2412
  Bottom Layer w20: C148.2@2258.45,2163.42 2259.95,2164.92 v1(2292.41,2164.92) 2299.52,2172.02 2299.52,2205.13 2313.33,2218.94
  Bottom Layer w22: v1(2377.88,1981.26) 2377.84,2037.83 2377.99,2037.97 C9.3@2377.99,2040.61
  other v1: 2423,1566 2463,1566 2414,1604.81 2414,1644.81 2414,1684 2414,1724 2414,1764 2458,1815.81 2458,1855.81 2300,2187.81 2152.97,2317.03 2348.64,2450.17 2470,2451.79 2373.75,2460.81 2443,2461.81 2335,2474.81 2359.5,2481.81 2388,2481.81 2471,2481.81 2435,2486.81
PVIN_LDO_LS1: C147.2 R107.2 R109.2 U8.12 | length 303.1
  Bottom Layer w10: 2157,2048.46 2165.04,2040.42 2203.25,2040.42 2211.29,2048.46 2273.07,2048.46 2343.61,2119 2370.11,2145.5 U8.12@2370.11,2188.63
QSPI_CS: R38.1 U1.1 U29.T6 | length 1073
  Top Layer w8: v1(2723,4719) 2723.24,4718.76 2723.24,4694.57 R38.1@2723.49,4694.33
  SIG1 w6: v1(2461,4414) 2461,4439.01 2461,4468.01 2467.5,4474.51 2495.5,4474.51 2502,4481.01 2502,4494.01 2495.5,4500.51 2467.5,4500.51 2461,4507.01 2461,4520.01 2467.5,4526.51 2494.01,4526.51 2500.51,4533.01 2500.51,4546.01 2494.01,4552.51 2467.5,4552.51 2461,4559.01 2461,4579 2461,4641 2539,4719 v1(2723,4719)
  Bottom Layer w4: U29.T6@2393.25,4077.38 2406.01,4090.14 2406.01,4269.12 2397.96,4277.18 2397.96,4281
  Bottom Layer w8: 2397.96,4281 2397.96,4350.96 v1(2461,4414) ; v1(2723,4719) 2723,4694.82 U1.1@2723.49,4694.33
QSPI_D0: R45.2 U29.U8 | length 964.8
  SIG1 w6: v1(2385,4543) 2385,4573.43 2398,4586.43 2398,4650.68 2446.16,4698.83 2458.09,4698.83 2472.99,4683.93 2472.99,4670.99 2449,4647 2449,4428.75 2435.69,4415.44 2400.44,4415.44 2385.82,4400.82 2385.82,4355.46 2401.28,4340 v1(2471,4340)
  Bottom Layer w4: U29.U8@2444.44,4102.97 2444.44,4282 2447.9,4285.47
  Bottom Layer w8: v1(2385,4543) 2385.67,4543.67 2409.61,4543.67 R45.2@2410.27,4544.33 ; 2447.9,4285.47 2471,4308.57 v1(2471,4340)
QSPI_D0_FLASH: R45.1 U1.5 | length 74.9
  Bottom Layer w8: R45.1@2433.89,4544.33 U1.5@2508.8,4544.33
